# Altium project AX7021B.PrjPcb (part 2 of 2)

## Sheet PAGE03 JTAG.SchDoc
size 386 x 279 mm
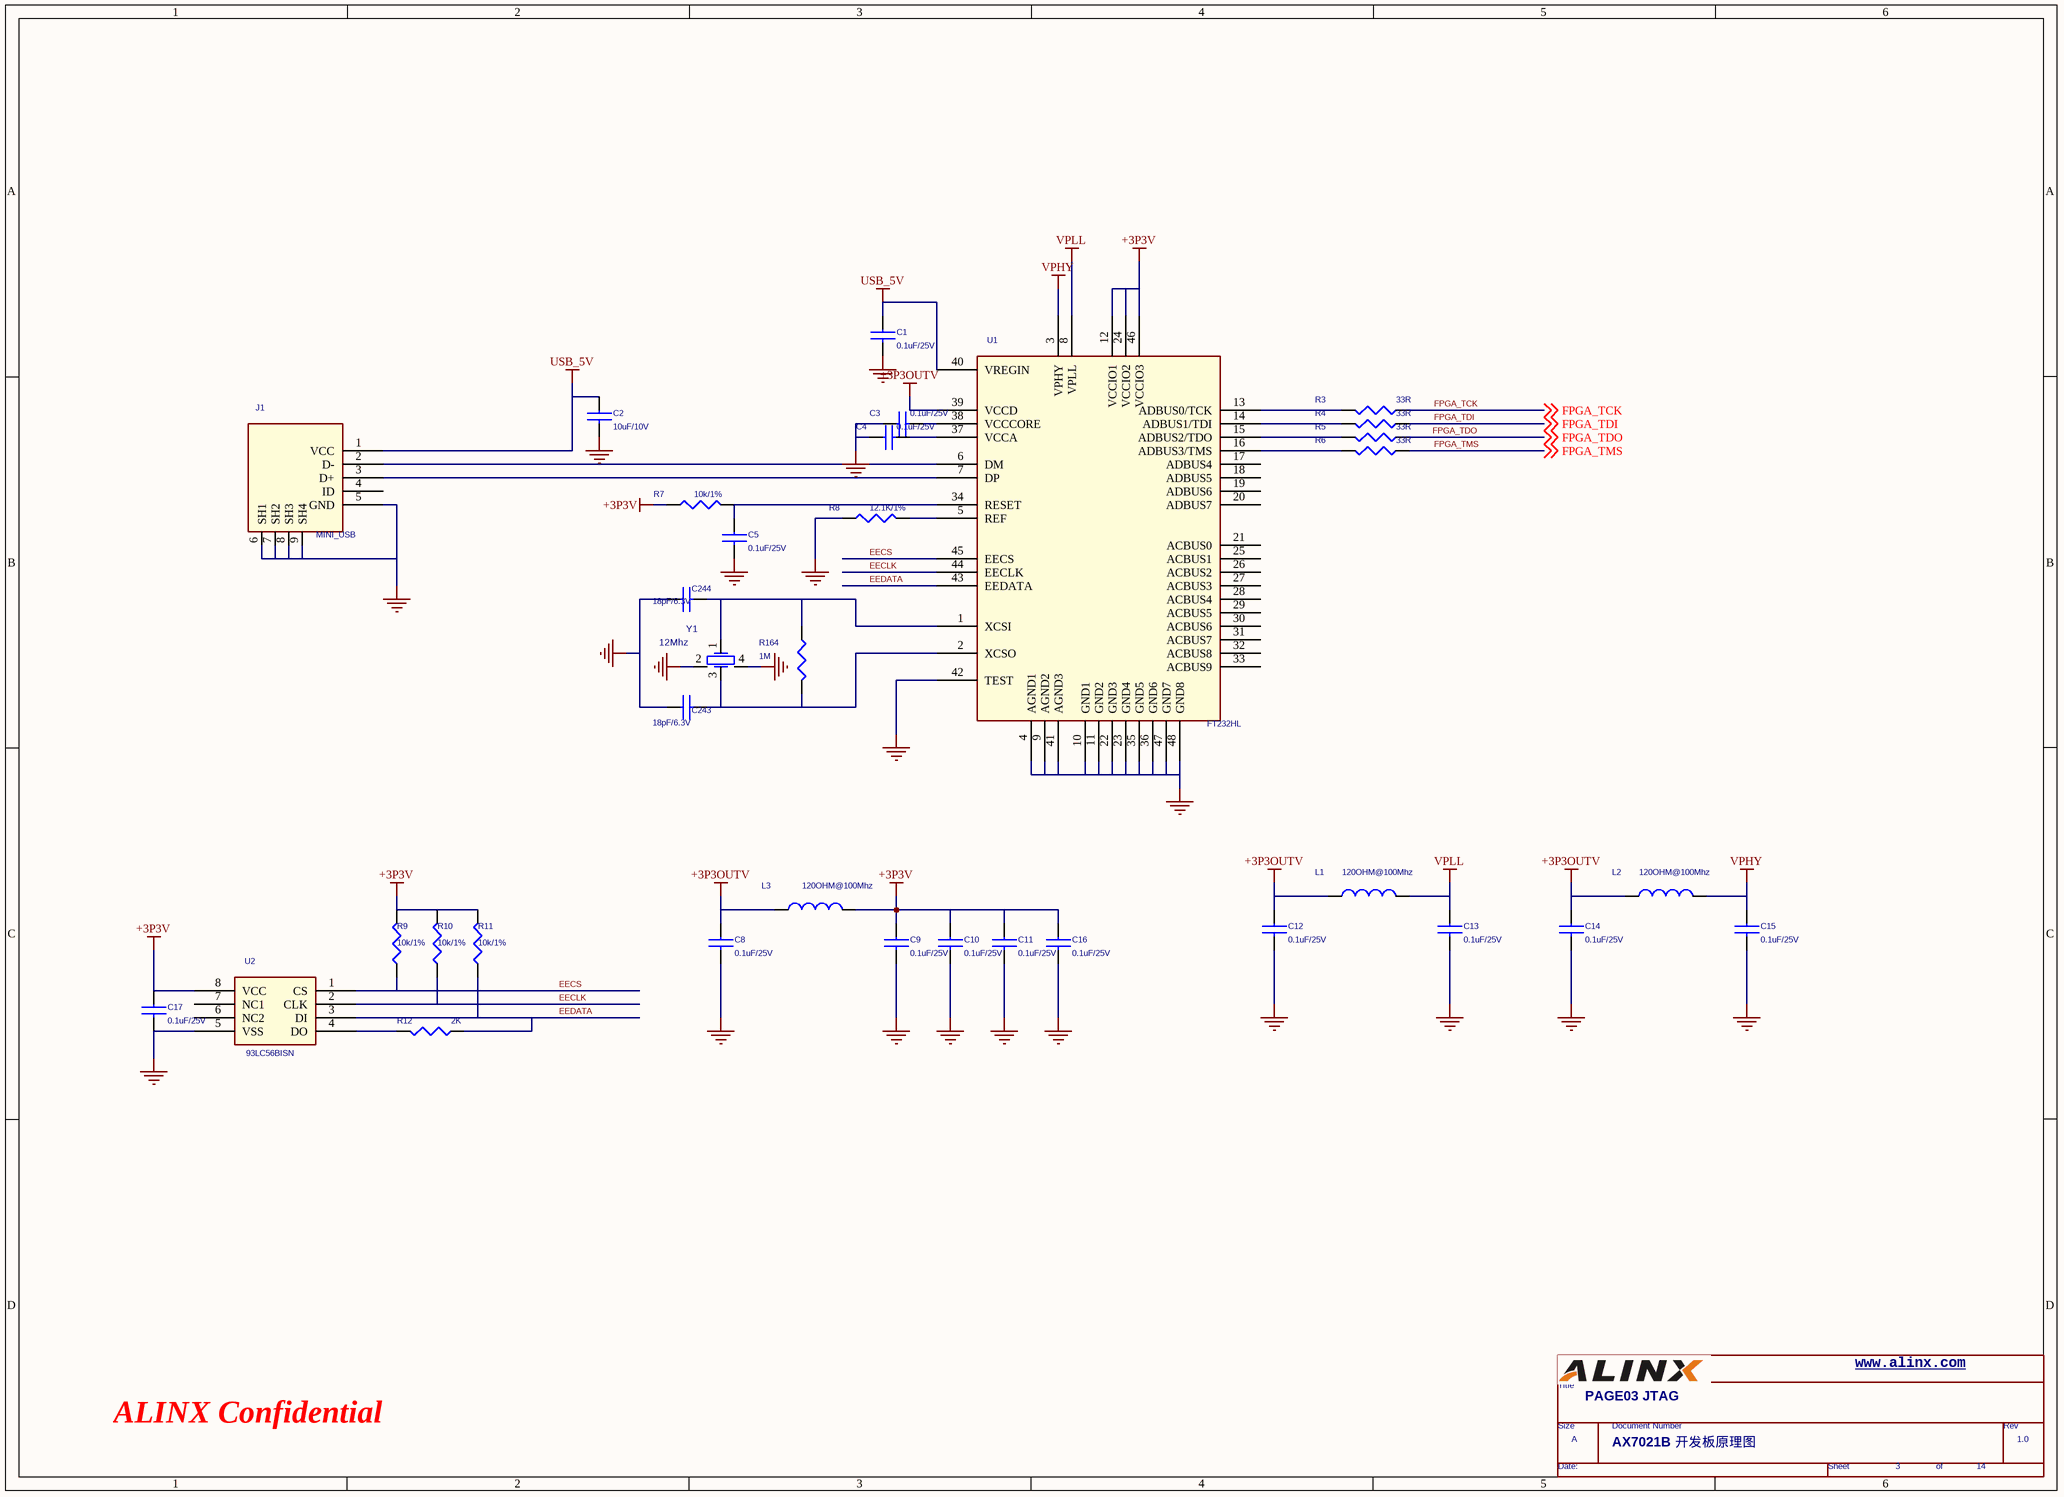
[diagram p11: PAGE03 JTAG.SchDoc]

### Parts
(Parts that share a designator on the sheet are numbered #1, #2 ... from top to bottom, then left to right.)
*#12  Doc: AX7021B 开发板原理图  RevCode: 1.0  Title: PAGE03 JTAG  Page Size: A  Page Number: 3  Page Count: 14  (hidden comment: TitleBlock0)  (graphical)
C1  0.1uF/25V  [C0402]
C2  10uF/10V  [C0603]
C3  0.1uF/25V  [C0402]
C4  0.1uF/25V  [C0402]
C5  0.1uF/25V  [C0402]
C8  0.1uF/25V  [C0402]
C9  0.1uF/25V  [C0402]
C10  0.1uF/25V  [C0402]
C11  0.1uF/25V  [C0402]
C12  0.1uF/25V  [C0402]
C13  0.1uF/25V  [C0402]
C14  0.1uF/25V  [C0402]
C15  0.1uF/25V  [C0402]
C16  0.1uF/25V  [C0402]
C17  0.1uF/25V  [C0402]
C243  18pF/6.3V  [C0402]
C244  18pF/6.3V  [C0402]
J1  MINI_USB  [mini_usb_dip]
L1  120OHM@100Mhz  [L0603]
L2  120OHM@100Mhz  [L0603]
L3  120OHM@100Mhz  [L0603]
R3  33R  [R0402]
R4  33R  [R0402]
R5  33R  [R0402]
R6  33R  [R0402]
R7  10k/1%  [R0402]
R8  12.1K/1%  [R0402]
R9  10k/1%  [R0402]
R10  10k/1%  [R0402]
R11  10k/1%  [R0402]
R12  2K  [R0402]
R164  1M  [R0402]
U1  FT232HL  [LQFP-48]
U2  93LC56BISN  [SO8]
Y1  12Mhz  [OSC3225]

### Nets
+3P3OUTV: C8.1 C12.1 C14.1 L1.1 L2.1 L3.1 U1.39(VCCD)
+3P3V: C9.1 C10.1 C11.1 C16.1 C17.1 L3.2 R7.1 R9.2 R10.2 R11.2 U1.12(VCCIO1) U1.24(VCCIO2) U1.46(VCCIO3) U2.8(VCC)
GND: C1.2 C2.2 C3.1 C4.1 C5.2 C8.2 C9.2 C10.2 C11.2 C12.2 C13.2 C14.2 C15.2 C16.2 C17.2 C243.1 C244.1 J1.5(GND) J1.6(SH1) J1.7(SH2) J1.8(SH3) J1.9(SH4) R8.1 U1.4(AGND1) U1.9(AGND2) U1.10(GND1) U1.11(GND2) U1.22(GND3) U1.23(GND4) U1.35(GND5) U1.36(GND6) U1.41(AGND3) U1.42(TEST) U1.47(GND7) U1.48(GND8) U2.5(VSS) Y1.2 Y1.4
USB_5V: C1.1 C2.1 J1.1(VCC) U1.40(VREGIN)
VPHY: C15.1 L2.2 U1.3(VPHY)
VPLL: C13.1 L1.2 U1.8(VPLL)
EECLK: R10.1 U1.44(EECLK) U2.2(CLK)
EECS: R9.1 U1.45(EECS) U2.1(CS)
EEDATA: R11.1 R12.1 U1.43(EEDATA) U2.3(DI)
FPGA_TCK: R3.1 ; off-sheet FPGA_TCK
FPGA_TDI: R4.1 ; off-sheet FPGA_TDI
FPGA_TDO: R5.1 ; off-sheet FPGA_TDO
FPGA_TMS: R6.1 ; off-sheet FPGA_TMS
NetC3_2: C3.2 U1.38(VCCCORE)
NetC4_2: C4.2 U1.37(VCCA)
NetC5_1: C5.1 R7.2 U1.34(RESET)
NetC243_2: C243.2 R164.1 U1.2(XCSO) Y1.3
NetC244_2: C244.2 R164.2 U1.1(XCSI) Y1.1
NetJ1_2: J1.2(D-) U1.6(DM)
NetJ1_3: J1.3(D+) U1.7(DP)
NetR3_2: R3.2 U1.13(ADBUS0/TCK)
NetR4_2: R4.2 U1.14(ADBUS1/TDI)
NetR5_2: R5.2 U1.15(ADBUS2/TDO)
NetR6_2: R6.2 U1.16(ADBUS3/TMS)
NetR8_2: R8.2 U1.5(REF)
NetR12_2: R12.2 U2.4(DO)

Not connected (* = marked no-connect by the designer): J1 4(ID); U1 17(ADBUS4) 18(ADBUS5) 19(ADBUS6) 20(ADBUS7) 21(ACBUS0) 25(ACBUS1) 26(ACBUS2) 27(ACBUS3) 28(ACBUS4) 29(ACBUS5) 30(ACBUS6) 31(ACBUS7) 32(ACBUS8) 33(ACBUS9); U2 6(NC2) 7(NC1)

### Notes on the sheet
- www.alinx.com
- ALINX Confidential

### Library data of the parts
C1-C5 C8-C17 C243 C244 = CAP NP: VA: 电容
J1 = USB_B_3: VA: 直插USB接口
L1-L3 = INDUCTOR_Dup1: VA: 磁珠
R3-R12 R164 = RESISTOR: VA: 电阻
U1 = FT232HL_0: VA: 芯片
U2 = 93LC56BISN_0: VA: 芯片
Y1 = X3_0_Dup1: VA: 无源晶振

## Sheet PAGE02 Board Connector.SchDoc
size 386 x 279 mm
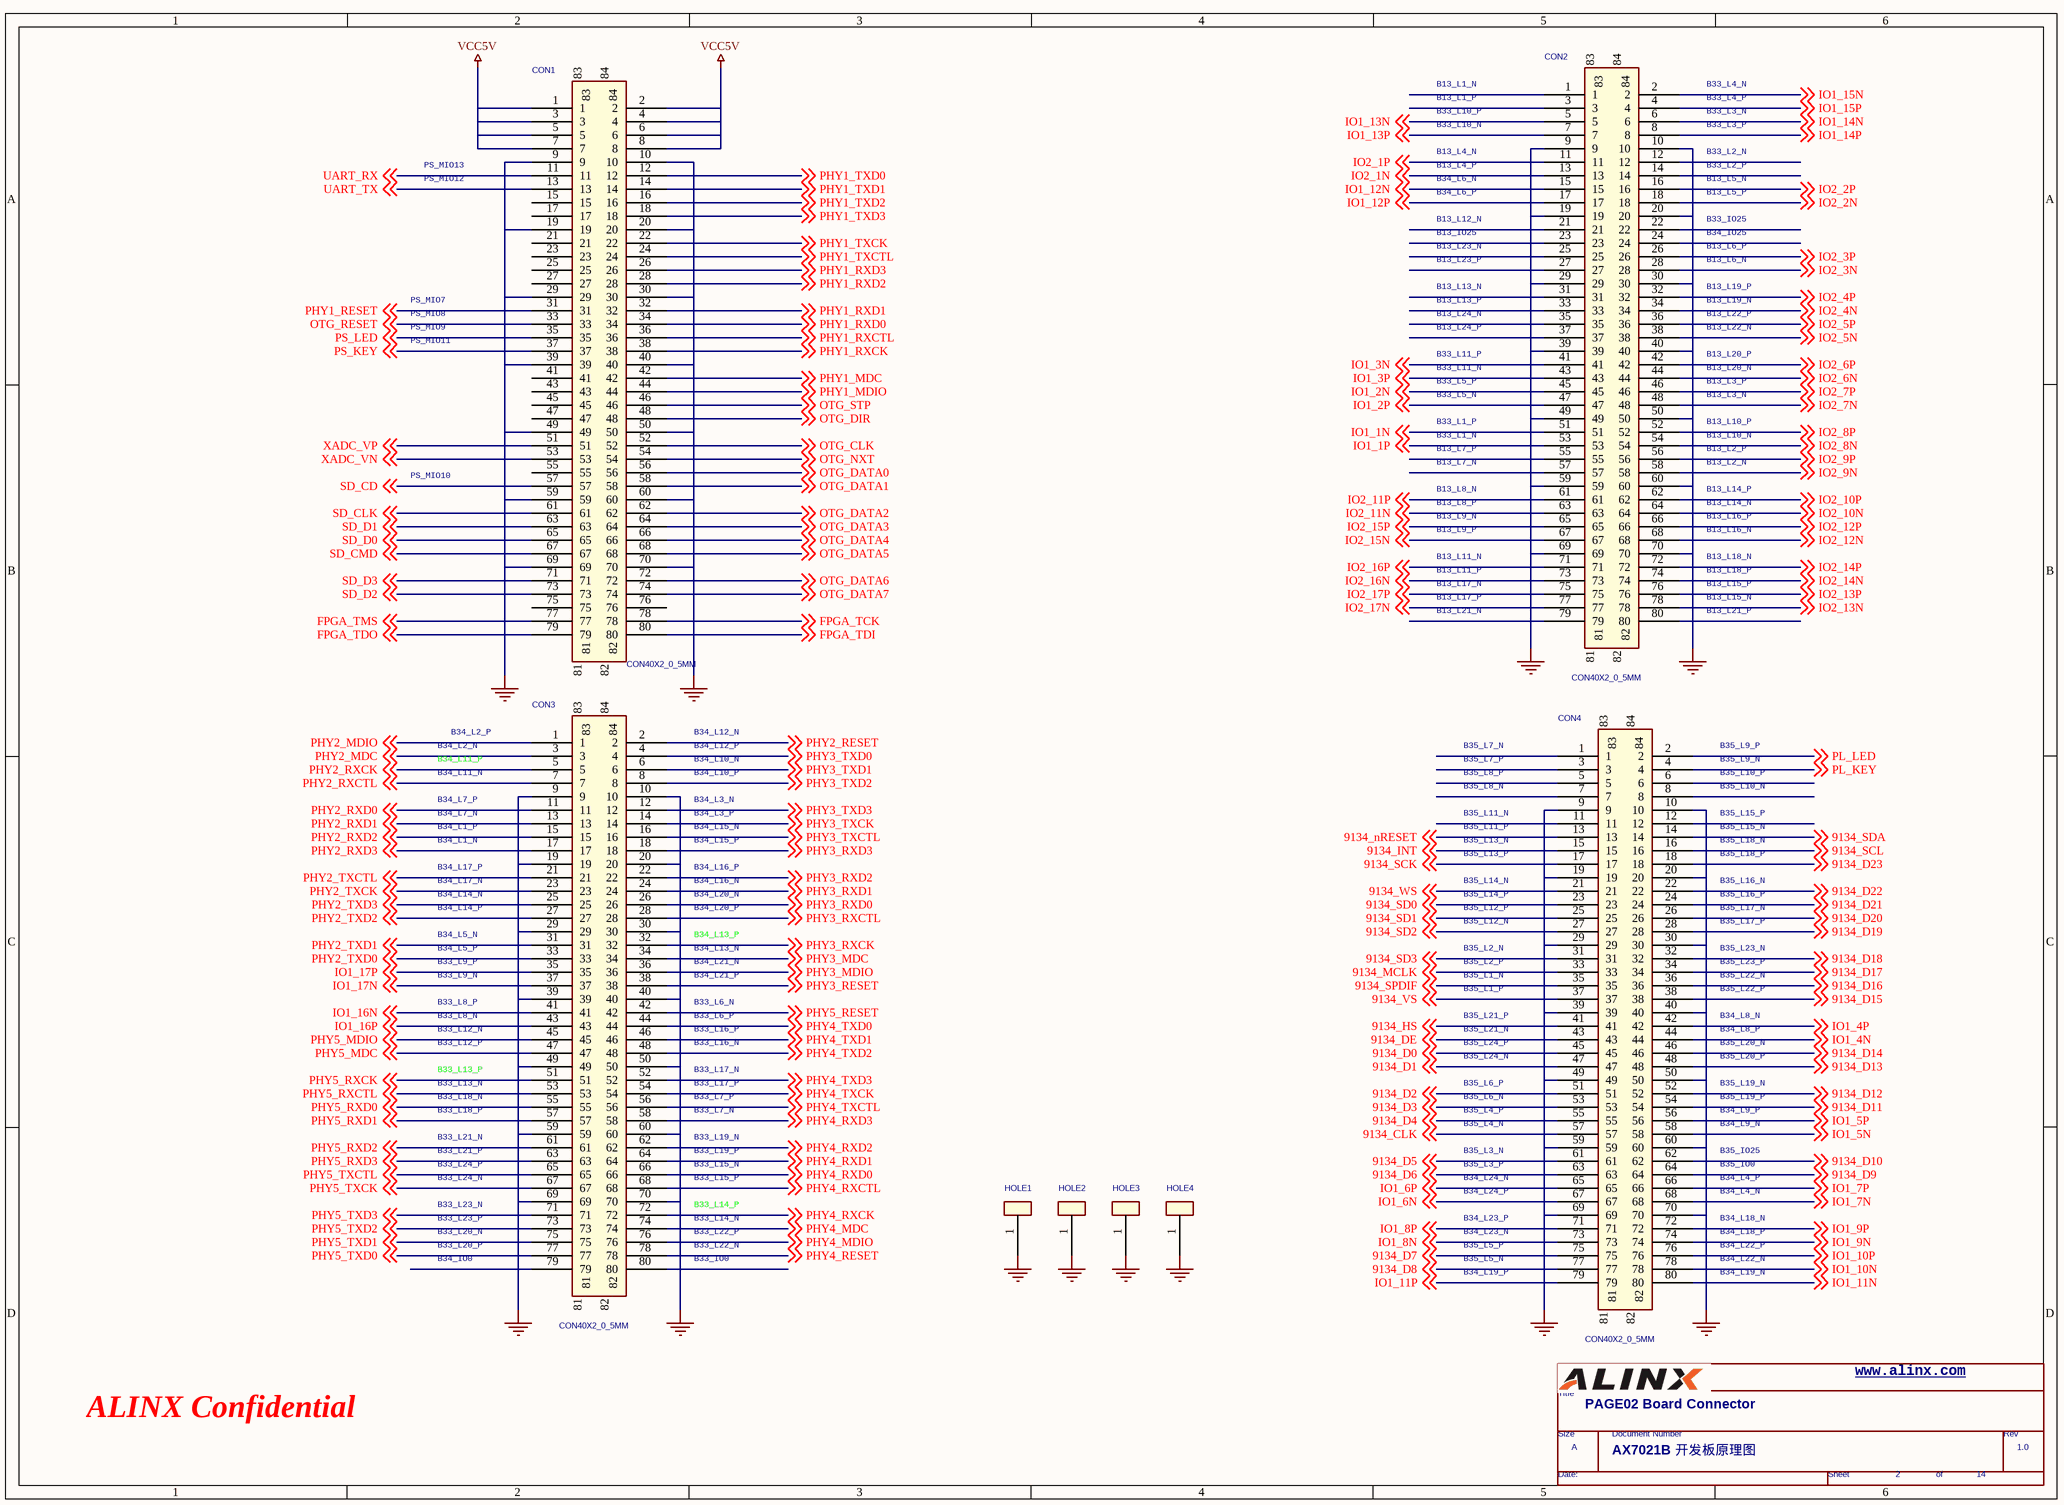
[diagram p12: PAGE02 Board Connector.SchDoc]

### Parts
(Parts that share a designator on the sheet are numbered #1, #2 ... from top to bottom, then left to right.)
*#13  Doc: AX7021B 开发板原理图  RevCode: 1.0  Title: PAGE02 Board Connector  Page Size: A  Page Number: 2  Page Count: 14  (hidden comment: TitleBlock0)  (graphical)
CON1  CON40X2_0_5MM  [CON40X2_0_8MM]
CON2  CON40X2_0_5MM  [CON40X2_0_8MM]
CON3  CON40X2_0_5MM  [CON40X2_0_8MM]
CON4  CON40X2_0_5MM  [CON40X2_0_8MM]
HOLE1  NC  [FPAD_1]  (value not drawn)
HOLE2  NC  [FPAD_1]  (value not drawn)
HOLE3  NC  [FPAD_1]  (value not drawn)
HOLE4  NC  [FPAD_1]  (value not drawn)

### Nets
GND: CON1.9 CON1.10 CON1.19 CON1.20 CON1.29 CON1.30 CON1.39 CON1.40 CON1.49 CON1.50 CON1.59 CON1.60 CON1.69 CON1.70 CON2.9 CON2.10 CON2.19 CON2.20 CON2.29 CON2.30 CON2.39 CON2.40 CON2.49 CON2.50 CON2.59 CON2.60 CON2.69 CON2.70 CON3.9 CON3.10 CON3.19 CON3.20 CON3.29 CON3.30 CON3.39 CON3.40 CON3.49 CON3.50 CON3.59 CON3.60 CON3.69 CON3.70 CON4.9 CON4.10 CON4.19 CON4.20 CON4.29 CON4.30 CON4.39 CON4.40 CON4.49 CON4.50 CON4.59 CON4.60 CON4.69 CON4.70 HOLE1.1 HOLE2.1 HOLE3.1 HOLE4.1
VCC5V: CON1.1 CON1.2 CON1.3 CON1.4 CON1.5 CON1.6 CON1.7 CON1.8
9134_CLK: CON4.57 ; off-sheet 9134_CLK
9134_D0: CON4.45 ; off-sheet 9134_D0
9134_D1: CON4.47 ; off-sheet 9134_D1
9134_D2: CON4.51 ; off-sheet 9134_D2
9134_D3: CON4.53 ; off-sheet 9134_D3
9134_D4: CON4.55 ; off-sheet 9134_D4
9134_D5: CON4.61 ; off-sheet 9134_D5
9134_D6: CON4.63 ; off-sheet 9134_D6
9134_D7: CON4.75 ; off-sheet 9134_D7
9134_D8: CON4.77 ; off-sheet 9134_D8
9134_D9: CON4.64 ; off-sheet 9134_D9
9134_D10: CON4.62 ; off-sheet 9134_D10
9134_D11: CON4.54 ; off-sheet 9134_D11
9134_D12: CON4.52 ; off-sheet 9134_D12
9134_D13: CON4.48 ; off-sheet 9134_D13
9134_D14: CON4.46 ; off-sheet 9134_D14
9134_D15: CON4.38 ; off-sheet 9134_D15
9134_D16: CON4.36 ; off-sheet 9134_D16
9134_D17: CON4.34 ; off-sheet 9134_D17
9134_D18: CON4.32 ; off-sheet 9134_D18
9134_D19: CON4.28 ; off-sheet 9134_D19
9134_D20: CON4.26 ; off-sheet 9134_D20
9134_D21: CON4.24 ; off-sheet 9134_D21
9134_D22: CON4.22 ; off-sheet 9134_D22
9134_D23: CON4.18 ; off-sheet 9134_D23
9134_DE: CON4.43 ; off-sheet 9134_DE
9134_HS: CON4.41 ; off-sheet 9134_HS
9134_INT: CON4.15 ; off-sheet 9134_INT
9134_MCLK: CON4.33 ; off-sheet 9134_MCLK
9134_nRESET: CON4.13 ; off-sheet 9134_nRESET
9134_SCK: CON4.17 ; off-sheet 9134_SCK
9134_SCL: CON4.16 ; off-sheet 9134_SCL
9134_SD0: CON4.23 ; off-sheet 9134_SD0
9134_SD1: CON4.25 ; off-sheet 9134_SD1
9134_SD2: CON4.27 ; off-sheet 9134_SD2
9134_SD3: CON4.31 ; off-sheet 9134_SD3
9134_SDA: CON4.14 ; off-sheet 9134_SDA
9134_SPDIF: CON4.35 ; off-sheet 9134_SPDIF
9134_VS: CON4.37 ; off-sheet 9134_VS
9134_WS: CON4.21 ; off-sheet 9134_WS
FPGA_TCK: CON1.78 ; off-sheet FPGA_TCK
FPGA_TDI: CON1.80 ; off-sheet FPGA_TDI
FPGA_TDO: CON1.79 ; off-sheet FPGA_TDO
FPGA_TMS: CON1.77 ; off-sheet FPGA_TMS
IO1_1N: CON2.51 ; off-sheet IO1_1N
IO1_1P: CON2.53 ; off-sheet IO1_1P
IO1_2N: CON2.45 ; off-sheet IO1_2N
IO1_2P: CON2.47 ; off-sheet IO1_2P
IO1_3N: CON2.41 ; off-sheet IO1_3N
IO1_3P: CON2.43 ; off-sheet IO1_3P
IO1_4N: CON4.44 ; off-sheet IO1_4N
IO1_4P: CON4.42 ; off-sheet IO1_4P
IO1_5N: CON4.58 ; off-sheet IO1_5N
IO1_5P: CON4.56 ; off-sheet IO1_5P
IO1_6N: CON4.67 ; off-sheet IO1_6N
IO1_6P: CON4.65 ; off-sheet IO1_6P
IO1_7N: CON4.68 ; off-sheet IO1_7N
IO1_7P: CON4.66 ; off-sheet IO1_7P
IO1_8N: CON4.73 ; off-sheet IO1_8N
IO1_8P: CON4.71 ; off-sheet IO1_8P
IO1_9N: CON4.74 ; off-sheet IO1_9N
IO1_9P: CON4.72 ; off-sheet IO1_9P
IO1_10N: CON4.78 ; off-sheet IO1_10N
IO1_10P: CON4.76 ; off-sheet IO1_10P
IO1_11N: CON4.80 ; off-sheet IO1_11N
IO1_11P: CON4.79 ; off-sheet IO1_11P
IO1_12N: CON2.15 ; off-sheet IO1_12N
IO1_12P: CON2.17 ; off-sheet IO1_12P
IO1_13N: CON2.5 ; off-sheet IO1_13N
IO1_13P: CON2.7 ; off-sheet IO1_13P
IO1_14N: CON2.6 ; off-sheet IO1_14N
IO1_14P: CON2.8 ; off-sheet IO1_14P
IO1_15N: CON2.2 ; off-sheet IO1_15N
IO1_15P: CON2.4 ; off-sheet IO1_15P
IO1_16N: CON3.41 ; off-sheet IO1_16N
IO1_16P: CON3.43 ; off-sheet IO1_16P
IO1_17N: CON3.37 ; off-sheet IO1_17N
IO1_17P: CON3.35 ; off-sheet IO1_17P
IO2_1N: CON2.13 ; off-sheet IO2_1N
IO2_1P: CON2.11 ; off-sheet IO2_1P
IO2_2N: CON2.18 ; off-sheet IO2_2N
IO2_2P: CON2.16 ; off-sheet IO2_2P
IO2_3N: CON2.28 ; off-sheet IO2_3N
IO2_3P: CON2.26 ; off-sheet IO2_3P
IO2_4N: CON2.34 ; off-sheet IO2_4N
IO2_4P: CON2.32 ; off-sheet IO2_4P
IO2_5N: CON2.38 ; off-sheet IO2_5N
IO2_5P: CON2.36 ; off-sheet IO2_5P
IO2_6N: CON2.44 ; off-sheet IO2_6N
IO2_6P: CON2.42 ; off-sheet IO2_6P
IO2_7N: CON2.48 ; off-sheet IO2_7N
IO2_7P: CON2.46 ; off-sheet IO2_7P
IO2_8N: CON2.54 ; off-sheet IO2_8N
IO2_8P: CON2.52 ; off-sheet IO2_8P
IO2_9N: CON2.58 ; off-sheet IO2_9N
IO2_9P: CON2.56 ; off-sheet IO2_9P
IO2_10N: CON2.64 ; off-sheet IO2_10N
IO2_10P: CON2.62 ; off-sheet IO2_10P
IO2_11N: CON2.63 ; off-sheet IO2_11N
IO2_11P: CON2.61 ; off-sheet IO2_11P
IO2_12N: CON2.68 ; off-sheet IO2_12N
IO2_12P: CON2.66 ; off-sheet IO2_12P
IO2_13N: CON2.78 ; off-sheet IO2_13N
IO2_13P: CON2.76 ; off-sheet IO2_13P
IO2_14N: CON2.74 ; off-sheet IO2_14N
IO2_14P: CON2.72 ; off-sheet IO2_14P
IO2_15N: CON2.67 ; off-sheet IO2_15N
IO2_15P: CON2.65 ; off-sheet IO2_15P
IO2_16N: CON2.73 ; off-sheet IO2_16N
IO2_16P: CON2.71 ; off-sheet IO2_16P
IO2_17N: CON2.77 ; off-sheet IO2_17N
IO2_17P: CON2.75 ; off-sheet IO2_17P
OTG_CLK: CON1.52 ; off-sheet OTG_CLK
OTG_DATA0: CON1.56 ; off-sheet OTG_DATA0
OTG_DATA1: CON1.58 ; off-sheet OTG_DATA1
OTG_DATA2: CON1.62 ; off-sheet OTG_DATA2
OTG_DATA3: CON1.64 ; off-sheet OTG_DATA3
OTG_DATA4: CON1.66 ; off-sheet OTG_DATA4
OTG_DATA5: CON1.68 ; off-sheet OTG_DATA5
OTG_DATA6: CON1.72 ; off-sheet OTG_DATA6
OTG_DATA7: CON1.74 ; off-sheet OTG_DATA7
OTG_DIR: CON1.48 ; off-sheet OTG_DIR
OTG_NXT: CON1.54 ; off-sheet OTG_NXT
OTG_RESET: CON1.33 ; off-sheet OTG_RESET
OTG_STP: CON1.46 ; off-sheet OTG_STP
PHY1_MDC: CON1.42 ; off-sheet PHY1_MDC
PHY1_MDIO: CON1.44 ; off-sheet PHY1_MDIO
PHY1_RESET: CON1.31 ; off-sheet PHY1_RESET
PHY1_RXCK: CON1.38 ; off-sheet PHY1_RXCK
PHY1_RXCTL: CON1.36 ; off-sheet PHY1_RXCTL
PHY1_RXD0: CON1.34 ; off-sheet PHY1_RXD0
PHY1_RXD1: CON1.32 ; off-sheet PHY1_RXD1
PHY1_RXD2: CON1.28 ; off-sheet PHY1_RXD2
PHY1_RXD3: CON1.26 ; off-sheet PHY1_RXD3
PHY1_TXCK: CON1.22 ; off-sheet PHY1_TXCK
PHY1_TXCTL: CON1.24 ; off-sheet PHY1_TXCTL
PHY1_TXD0: CON1.12 ; off-sheet PHY1_TXD0
PHY1_TXD1: CON1.14 ; off-sheet PHY1_TXD1
PHY1_TXD2: CON1.16 ; off-sheet PHY1_TXD2
PHY1_TXD3: CON1.18 ; off-sheet PHY1_TXD3
PHY2_MDC: CON3.3 ; off-sheet PHY2_MDC
PHY2_MDIO: CON3.1 ; off-sheet PHY2_MDIO
PHY2_RESET: CON3.2 ; off-sheet PHY2_RESET
PHY2_RXCK: CON3.5 ; off-sheet PHY2_RXCK
PHY2_RXCTL: CON3.7 ; off-sheet PHY2_RXCTL
PHY2_RXD0: CON3.11 ; off-sheet PHY2_RXD0
PHY2_RXD1: CON3.13 ; off-sheet PHY2_RXD1
PHY2_RXD2: CON3.15 ; off-sheet PHY2_RXD2
PHY2_RXD3: CON3.17 ; off-sheet PHY2_RXD3
PHY2_TXCK: CON3.23 ; off-sheet PHY2_TXCK
PHY2_TXCTL: CON3.21 ; off-sheet PHY2_TXCTL
PHY2_TXD0: CON3.33 ; off-sheet PHY2_TXD0
PHY2_TXD1: CON3.31 ; off-sheet PHY2_TXD1
PHY2_TXD2: CON3.27 ; off-sheet PHY2_TXD2
PHY2_TXD3: CON3.25 ; off-sheet PHY2_TXD3
PHY3_MDC: CON3.34 ; off-sheet PHY3_MDC
PHY3_MDIO: CON3.36 ; off-sheet PHY3_MDIO
PHY3_RESET: CON3.38 ; off-sheet PHY3_RESET
PHY3_RXCK: CON3.32 ; off-sheet PHY3_RXCK
PHY3_RXCTL: CON3.28 ; off-sheet PHY3_RXCTL
PHY3_RXD0: CON3.26 ; off-sheet PHY3_RXD0
PHY3_RXD1: CON3.24 ; off-sheet PHY3_RXD1
PHY3_RXD2: CON3.22 ; off-sheet PHY3_RXD2
PHY3_RXD3: CON3.18 ; off-sheet PHY3_RXD3
PHY3_TXCK: CON3.14 ; off-sheet PHY3_TXCK
PHY3_TXCTL: CON3.16 ; off-sheet PHY3_TXCTL
PHY3_TXD0: CON3.4 ; off-sheet PHY3_TXD0
PHY3_TXD1: CON3.6 ; off-sheet PHY3_TXD1
PHY3_TXD2: CON3.8 ; off-sheet PHY3_TXD2
PHY3_TXD3: CON3.12 ; off-sheet PHY3_TXD3
PHY4_MDC: CON3.74 ; off-sheet PHY4_MDC
PHY4_MDIO: CON3.76 ; off-sheet PHY4_MDIO
PHY4_RESET: CON3.78 ; off-sheet PHY4_RESET
PHY4_RXCK: CON3.72 ; off-sheet PHY4_RXCK
PHY4_RXCTL: CON3.68 ; off-sheet PHY4_RXCTL
PHY4_RXD0: CON3.66 ; off-sheet PHY4_RXD0
PHY4_RXD1: CON3.64 ; off-sheet PHY4_RXD1
PHY4_RXD2: CON3.62 ; off-sheet PHY4_RXD2
PHY4_RXD3: CON3.58 ; off-sheet PHY4_RXD3
PHY4_TXCK: CON3.54 ; off-sheet PHY4_TXCK
PHY4_TXCTL: CON3.56 ; off-sheet PHY4_TXCTL
PHY4_TXD0: CON3.44 ; off-sheet PHY4_TXD0
PHY4_TXD1: CON3.46 ; off-sheet PHY4_TXD1
PHY4_TXD2: CON3.48 ; off-sheet PHY4_TXD2
PHY4_TXD3: CON3.52 ; off-sheet PHY4_TXD3
PHY5_MDC: CON3.47 ; off-sheet PHY5_MDC
PHY5_MDIO: CON3.45 ; off-sheet PHY5_MDIO
PHY5_RESET: CON3.42 ; off-sheet PHY5_RESET
PHY5_RXCK: CON3.51 ; off-sheet PHY5_RXCK
PHY5_RXCTL: CON3.53 ; off-sheet PHY5_RXCTL
PHY5_RXD0: CON3.55 ; off-sheet PHY5_RXD0
PHY5_RXD1: CON3.57 ; off-sheet PHY5_RXD1
PHY5_RXD2: CON3.61 ; off-sheet PHY5_RXD2
PHY5_RXD3: CON3.63 ; off-sheet PHY5_RXD3
PHY5_TXCK: CON3.67 ; off-sheet PHY5_TXCK
PHY5_TXCTL: CON3.65 ; off-sheet PHY5_TXCTL
PHY5_TXD0: CON3.77 ; off-sheet PHY5_TXD0
PHY5_TXD1: CON3.75 ; off-sheet PHY5_TXD1
PHY5_TXD2: CON3.73 ; off-sheet PHY5_TXD2
PHY5_TXD3: CON3.71 ; off-sheet PHY5_TXD3
PL_KEY: CON4.4 ; off-sheet PL_KEY
PL_LED: CON4.2 ; off-sheet PL_LED
PS_KEY: CON1.37 ; off-sheet PS_KEY
PS_LED: CON1.35 ; off-sheet PS_LED
SD_CD: CON1.57 ; off-sheet SD_CD
SD_CLK: CON1.61 ; off-sheet SD_CLK
SD_CMD: CON1.67 ; off-sheet SD_CMD
SD_D0: CON1.65 ; off-sheet SD_D0
SD_D1: CON1.63 ; off-sheet SD_D1
SD_D2: CON1.73 ; off-sheet SD_D2
SD_D3: CON1.71 ; off-sheet SD_D3
UART_RX: CON1.11 ; off-sheet UART_RX
UART_TX: CON1.13 ; off-sheet UART_TX
XADC_VN: CON1.53 ; off-sheet XADC_VN
XADC_VP: CON1.51 ; off-sheet XADC_VP

Not connected (* = marked no-connect by the designer): CON1 15 17 21 23 25 27 41 43 45 47 55 75 76 81 82 83 84; CON2 1 3 12 14 21 22 23 24 25 27 31 33 35 37 55 57 79 80 81 82 83 84; CON3 79 80 81 82 83 84; CON4 1 3 5 6 7 8 11 12 81 82 83 84

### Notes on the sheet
- B13_L1_N
- B13_L1_P
- B33_L4_N
- B33_L4_P
- PS_MIO13
- B33_L10_P
- B33_L10_N
- B13_L4_N
- B13_L4_P
- B33_L3_P
- B33_L3_N
- B33_L2_N
- B33_L2_P
- PS_MIO12
- B13_L12_N
- B34_L6_N
- B13_IO25
- B34_L6_P
- B33_IO25
- B13_L5_P
- B13_L5_N
- B34_IO25
- PS_MIO7
- B13_L13_N
- B13_L13_P
- B13_L23_P
- B13_L23_N
- B13_L6_N
- B13_L6_P
- B13_L19_P
- B13_L19_N
- PS_MIO11
- PS_MIO8
- PS_MIO9
- B33_L11_N
- B33_L11_P
- B13_L24_N
- B13_L24_P
- B13_L20_P
- B13_L20_N
- B13_L22_P
- B13_L22_N
- B33_L5_N
- B33_L5_P
- B33_L1_P
- B33_L1_N
- B13_L10_P
- B13_L10_N
- B13_L3_P
- B13_L3_N
- PS_MIO10
- B13_L7_N
- B13_L7_P
- B13_L8_N
- B13_L8_P
- B13_L14_P
- B13_L14_N
- B13_L2_P
- B13_L2_N
- B13_L9_N
- B13_L9_P
- B13_L11_N
- B13_L11_P
- B13_L16_P
- B13_L16_N
- B13_L18_N
- B13_L18_P
- B13_L17_N
- B13_L17_P
- B13_L21_N
- B13_L15_P
- B13_L15_N
- B13_L21_P
- B34_L2_N
- B34_L11_N
- B34_L11_P
- B34_L2_P
- B34_L12_N
- B34_L12_P
- B34_L10_P
- B34_L10_N
- B35_L7_N
- B35_L7_P
- B35_L8_P
- B35_L10_P
- B35_L9_P
- B35_L9_N
- B34_L7_P
- B34_L7_N
- B34_L1_N
- B34_L1_P
- B34_L3_N
- B34_L3_P
- B34_L15_N
- B34_L15_P
- B35_L8_N
- B35_L11_N
- B35_L11_P
- B35_L13_N
- B35_L18_N
- B35_L15_P
- B35_L15_N
- B35_L10_N
- B34_L17_N
- B34_L17_P
- B34_L14_N
- B34_L14_P
- B34_L20_N
- B34_L20_P
- B34_L16_N
- B34_L16_P
- B35_L13_P
- B35_L14_N
- B35_L14_P
- B35_L12_P
- B35_L17_N
- B35_L16_N
- B35_L16_P
- B35_L18_P
- B33_L9_N
- B34_L5_N
- B34_L5_P
- B33_L9_P
- B34_L21_P
- B34_L21_N
- B34_L13_N
- B34_L13_P
- B35_L12_N
- B35_L1_N
- B35_L2_N
- B35_L2_P
- B35_L23_N
- B35_L23_P
- B35_L22_N
- B35_L17_P
- B33_L8_P
- B33_L8_N
- B33_L12_N
- B33_L12_P
- B33_L16_N
- B33_L16_P
- B33_L6_N
- B33_L6_P
- B35_L24_P
- B35_L21_P
- B35_L21_N
- B35_L1_P
- B35_L20_N
- B34_L8_P
- B34_L8_N
- B35_L22_P
- B33_L18_N
- B33_L18_P
- B33_L13_P
- B33_L13_N
- B33_L17_N
- B33_L17_P
- B33_L7_N
- B33_L7_P
- B35_L24_N
- B35_L6_P
- B35_L6_N
- B35_L4_P
- B34_L9_P
- B35_L19_P
- B35_L19_N
- B35_L20_P
- B33_L21_P
- B33_L24_P
- B33_L24_N
- B33_L21_N
- B33_L15_P
- B33_L15_N
- B33_L19_N
- B33_L19_P
- B34_L24_N
- B35_L4_N
- B35_L3_N
- B35_L3_P
- B35_IO25
- B35_IO0
- B34_L4_P
- B34_L9_N
- B33_L23_N
- B33_L23_P
- B33_L20_N
- B33_L20_P
- B33_L22_P
- B33_L22_N
- B33_L14_N
- B33_L14_P
- B34_L23_P
- B34_L23_N
- B34_L24_P
- B35_L5_P
- B34_L22_P
- B34_L18_P
- B34_L18_N
- B34_L4_N
- B34_IO0
- B33_IO0
- B35_L5_N
- B34_L19_P
- B34_L22_N
- B34_L19_N
- www.alinx.com
- ALINX Confidential

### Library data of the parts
CON1-CON4 = CON40X2_0_1: VA: 2x40PIN连接器底板
HOLE1-HOLE4 = TEST POINT

## Sheet PAGE01 Block Diagram.SchDoc
size 406 x 304 mm
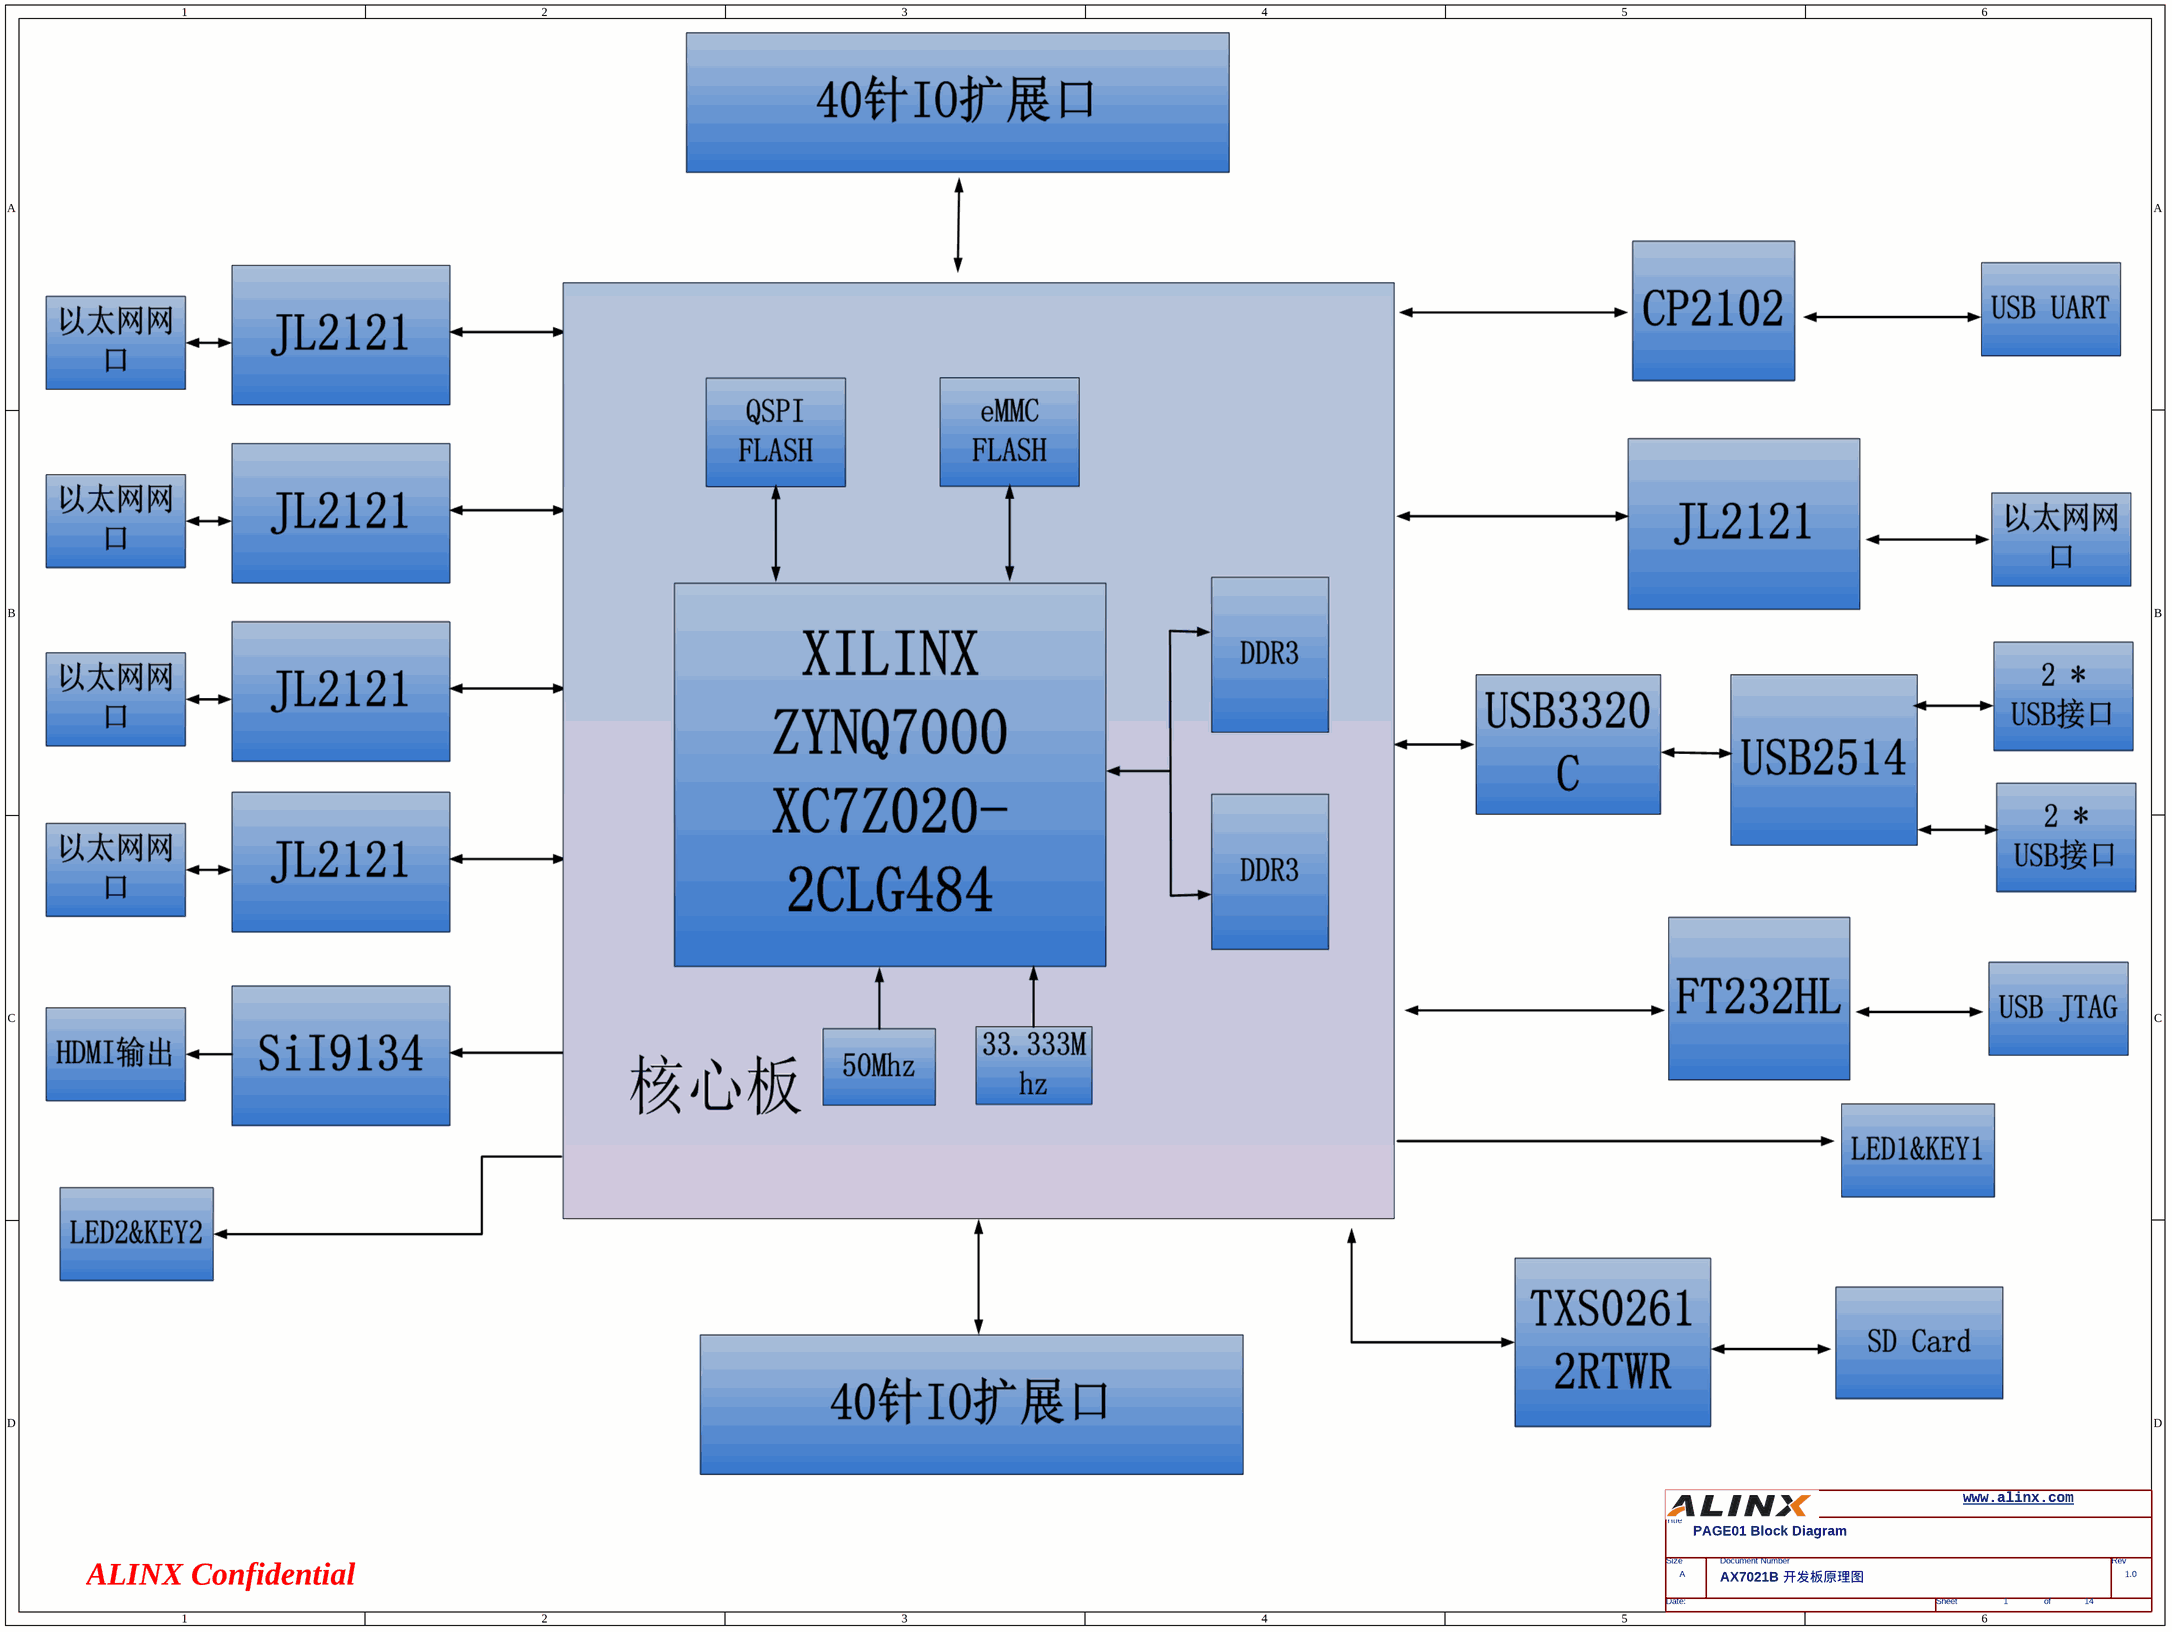
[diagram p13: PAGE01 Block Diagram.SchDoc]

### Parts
(Parts that share a designator on the sheet are numbered #1, #2 ... from top to bottom, then left to right.)
*#14  Doc: AX7021B 开发板原理图  RevCode: 1.0  Title: PAGE01 Block Diagram  Page Size: A  Page Number: 1  Page Count: 14  (hidden comment: TitleBlock0)  (graphical)

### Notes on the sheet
- www.alinx.com
- ALINX Confidential

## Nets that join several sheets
GND: PAGE14 Power (33 pins), PAGE13 EX Connector (10 pins), PAGE12 KEY and LED (KEY1.1 KEY1.2 KEY2.1 KEY2.2), PAGE11 PL Ethernet5 (32 pins), PAGE10 PL Ethernet4 (32 pins), PAGE09 PL Ethernet3 (32 pins), PAGE08 PL Ethernet2 (32 pins), PAGE07 HDMI OUT (51 pins), PAGE06 HOST USB X 4 (58 pins), PAGE05 PS Ethernet1 (30 pins), PAGE04 SD Card and UART (24 pins), PAGE03 JTAG (38 pins), PAGE02 Board Connector (60 pins)
RGMII_VCC: PAGE14 Power (C187.1 C188.1 U19.5), PAGE11 PL Ethernet5 (L81.1), PAGE10 PL Ethernet4 (L77.1), PAGE09 PL Ethernet3 (L73.1), PAGE08 PL Ethernet2 (L69.1)
VCC1V8: PAGE14 Power (7 pins), PAGE07 HDMI OUT (C81.1 L8.2 L9.2), PAGE06 HOST USB X 4 (10 pins), PAGE05 PS Ethernet1 (L65.1), PAGE04 SD Card and UART (C24.1 U5.5)
VCC3V3: PAGE14 Power (7 pins), PAGE13 EX Connector (6 pins), PAGE12 KEY and LED (LED1.1 LED2.1 R119.2 R123.2), PAGE11 PL Ethernet5 (6 pins), PAGE10 PL Ethernet4 (6 pins), PAGE09 PL Ethernet3 (6 pins), PAGE08 PL Ethernet2 (6 pins), PAGE07 HDMI OUT (L7.1 R48.2 R49.2), PAGE06 HOST USB X 4 (19 pins), PAGE05 PS Ethernet1 (8 pins), PAGE04 SD Card and UART (14 pins)
VCC5V: PAGE14 Power (11 pins), PAGE13 EX Connector (C190.1 C192.1 J15.2 J16.2), PAGE07 HDMI OUT (F1.1 U9.45), PAGE06 HOST USB X 4 (C61.1 U8.5), PAGE02 Board Connector (8 pins)
9134_CLK: PAGE07 HDMI OUT (U9.88), PAGE02 Board Connector (CON4.57)
9134_D0: PAGE07 HDMI OUT (U9.94), PAGE02 Board Connector (CON4.45)
9134_D1: PAGE07 HDMI OUT (U9.93), PAGE02 Board Connector (CON4.47)
9134_D2: PAGE07 HDMI OUT (U9.92), PAGE02 Board Connector (CON4.51)
9134_D3: PAGE07 HDMI OUT (U9.91), PAGE02 Board Connector (CON4.53)
9134_D4: PAGE07 HDMI OUT (U9.90), PAGE02 Board Connector (CON4.55)
9134_D5: PAGE07 HDMI OUT (U9.86), PAGE02 Board Connector (CON4.61)
9134_D6: PAGE07 HDMI OUT (U9.85), PAGE02 Board Connector (CON4.63)
9134_D7: PAGE07 HDMI OUT (U9.84), PAGE02 Board Connector (CON4.75)
9134_D8: PAGE07 HDMI OUT (U9.79), PAGE02 Board Connector (CON4.77)
9134_D9: PAGE07 HDMI OUT (U9.78), PAGE02 Board Connector (CON4.64)
9134_D10: PAGE07 HDMI OUT (U9.77), PAGE02 Board Connector (CON4.62)
9134_D11: PAGE07 HDMI OUT (U9.75), PAGE02 Board Connector (CON4.54)
9134_D12: PAGE07 HDMI OUT (U9.74), PAGE02 Board Connector (CON4.52)
9134_D13: PAGE07 HDMI OUT (U9.73), PAGE02 Board Connector (CON4.48)
9134_D14: PAGE07 HDMI OUT (U9.72), PAGE02 Board Connector (CON4.46)
9134_D15: PAGE07 HDMI OUT (U9.71), PAGE02 Board Connector (CON4.38)
9134_D16: PAGE07 HDMI OUT (U9.63), PAGE02 Board Connector (CON4.36)
9134_D17: PAGE07 HDMI OUT (U9.62), PAGE02 Board Connector (CON4.34)
9134_D18: PAGE07 HDMI OUT (U9.61), PAGE02 Board Connector (CON4.32)
9134_D19: PAGE07 HDMI OUT (U9.60), PAGE02 Board Connector (CON4.28)
9134_D20: PAGE07 HDMI OUT (U9.59), PAGE02 Board Connector (CON4.26)
9134_D21: PAGE07 HDMI OUT (U9.58), PAGE02 Board Connector (CON4.24)
9134_D22: PAGE07 HDMI OUT (U9.57), PAGE02 Board Connector (CON4.22)
9134_D23: PAGE07 HDMI OUT (U9.56), PAGE02 Board Connector (CON4.18)
9134_DE: PAGE07 HDMI OUT (U9.1), PAGE02 Board Connector (CON4.43)
9134_HS: PAGE07 HDMI OUT (U9.2), PAGE02 Board Connector (CON4.41)
9134_INT: PAGE07 HDMI OUT (U9.24), PAGE02 Board Connector (CON4.15)
9134_MCLK: PAGE07 HDMI OUT (U9.5), PAGE02 Board Connector (CON4.33)
9134_nRESET: PAGE07 HDMI OUT (U9.25), PAGE02 Board Connector (CON4.13)
9134_SCK: PAGE07 HDMI OUT (U9.11), PAGE02 Board Connector (CON4.17)
9134_SCL: PAGE07 HDMI OUT (R48.1 U9.48), PAGE02 Board Connector (CON4.16)
9134_SD0: PAGE07 HDMI OUT (U9.9), PAGE02 Board Connector (CON4.23)
9134_SD1: PAGE07 HDMI OUT (U9.8), PAGE02 Board Connector (CON4.25)
9134_SD2: PAGE07 HDMI OUT (U9.7), PAGE02 Board Connector (CON4.27)
9134_SD3: PAGE07 HDMI OUT (U9.6), PAGE02 Board Connector (CON4.31)
9134_SDA: PAGE07 HDMI OUT (R49.1 U9.49), PAGE02 Board Connector (CON4.14)
9134_SPDIF: PAGE07 HDMI OUT (U9.4), PAGE02 Board Connector (CON4.35)
9134_VS: PAGE07 HDMI OUT (U9.3), PAGE02 Board Connector (CON4.37)
9134_WS: PAGE07 HDMI OUT (U9.10), PAGE02 Board Connector (CON4.21)
FPGA_TCK: PAGE03 JTAG (R3.1), PAGE02 Board Connector (CON1.78)
FPGA_TDI: PAGE03 JTAG (R4.1), PAGE02 Board Connector (CON1.80)
FPGA_TDO: PAGE03 JTAG (R5.1), PAGE02 Board Connector (CON1.79)
FPGA_TMS: PAGE03 JTAG (R6.1), PAGE02 Board Connector (CON1.77)
IO1_1N: PAGE13 EX Connector (RN1.3), PAGE02 Board Connector (CON2.51)
IO1_1P: PAGE13 EX Connector (RN1.4), PAGE02 Board Connector (CON2.53)
IO1_2N: PAGE13 EX Connector (RN1.1), PAGE02 Board Connector (CON2.45)
IO1_2P: PAGE13 EX Connector (RN1.2), PAGE02 Board Connector (CON2.47)
IO1_3N: PAGE13 EX Connector (RN3.3), PAGE02 Board Connector (CON2.41)
IO1_3P: PAGE13 EX Connector (RN3.4), PAGE02 Board Connector (CON2.43)
IO1_4N: PAGE13 EX Connector (RN3.1), PAGE02 Board Connector (CON4.44)
IO1_4P: PAGE13 EX Connector (RN3.2), PAGE02 Board Connector (CON4.42)
IO1_5N: PAGE13 EX Connector (RN5.3), PAGE02 Board Connector (CON4.58)
IO1_5P: PAGE13 EX Connector (RN5.4), PAGE02 Board Connector (CON4.56)
IO1_6N: PAGE13 EX Connector (RN5.1), PAGE02 Board Connector (CON4.67)
IO1_6P: PAGE13 EX Connector (RN5.2), PAGE02 Board Connector (CON4.65)
IO1_7N: PAGE13 EX Connector (RN7.3), PAGE02 Board Connector (CON4.68)
IO1_7P: PAGE13 EX Connector (RN7.4), PAGE02 Board Connector (CON4.66)
IO1_8N: PAGE13 EX Connector (RN7.1), PAGE02 Board Connector (CON4.73)
IO1_8P: PAGE13 EX Connector (RN7.2), PAGE02 Board Connector (CON4.71)
IO1_9N: PAGE13 EX Connector (RN9.3), PAGE02 Board Connector (CON4.74)
IO1_9P: PAGE13 EX Connector (RN9.4), PAGE02 Board Connector (CON4.72)
IO1_10N: PAGE13 EX Connector (RN9.1), PAGE02 Board Connector (CON4.78)
IO1_10P: PAGE13 EX Connector (RN9.2), PAGE02 Board Connector (CON4.76)
IO1_11N: PAGE13 EX Connector (RN11.3), PAGE02 Board Connector (CON4.80)
IO1_11P: PAGE13 EX Connector (RN11.4), PAGE02 Board Connector (CON4.79)
IO1_12N: PAGE13 EX Connector (RN11.1), PAGE02 Board Connector (CON2.15)
IO1_12P: PAGE13 EX Connector (RN11.2), PAGE02 Board Connector (CON2.17)
IO1_13N: PAGE13 EX Connector (RN13.3), PAGE02 Board Connector (CON2.5)
IO1_13P: PAGE13 EX Connector (RN13.4), PAGE02 Board Connector (CON2.7)
IO1_14N: PAGE13 EX Connector (RN13.1), PAGE02 Board Connector (CON2.6)
IO1_14P: PAGE13 EX Connector (RN13.2), PAGE02 Board Connector (CON2.8)
IO1_15N: PAGE13 EX Connector (RN15.3), PAGE02 Board Connector (CON2.2)
IO1_15P: PAGE13 EX Connector (RN15.4), PAGE02 Board Connector (CON2.4)
IO1_16N: PAGE13 EX Connector (RN15.1), PAGE02 Board Connector (CON3.41)
IO1_16P: PAGE13 EX Connector (RN15.2), PAGE02 Board Connector (CON3.43)
IO1_17N: PAGE13 EX Connector (RN17.1), PAGE02 Board Connector (CON3.37)
IO1_17P: PAGE13 EX Connector (RN17.2), PAGE02 Board Connector (CON3.35)
IO2_1N: PAGE13 EX Connector (RN2.3), PAGE02 Board Connector (CON2.13)
IO2_1P: PAGE13 EX Connector (RN2.4), PAGE02 Board Connector (CON2.11)
IO2_2N: PAGE13 EX Connector (RN2.1), PAGE02 Board Connector (CON2.18)
IO2_2P: PAGE13 EX Connector (RN2.2), PAGE02 Board Connector (CON2.16)
IO2_3N: PAGE13 EX Connector (RN4.3), PAGE02 Board Connector (CON2.28)
IO2_3P: PAGE13 EX Connector (RN4.4), PAGE02 Board Connector (CON2.26)
IO2_4N: PAGE13 EX Connector (RN4.1), PAGE02 Board Connector (CON2.34)
IO2_4P: PAGE13 EX Connector (RN4.2), PAGE02 Board Connector (CON2.32)
IO2_5N: PAGE13 EX Connector (RN6.3), PAGE02 Board Connector (CON2.38)
IO2_5P: PAGE13 EX Connector (RN6.4), PAGE02 Board Connector (CON2.36)
IO2_6N: PAGE13 EX Connector (RN6.1), PAGE02 Board Connector (CON2.44)
IO2_6P: PAGE13 EX Connector (RN6.2), PAGE02 Board Connector (CON2.42)
IO2_7N: PAGE13 EX Connector (RN8.3), PAGE02 Board Connector (CON2.48)
IO2_7P: PAGE13 EX Connector (RN8.4), PAGE02 Board Connector (CON2.46)
IO2_8N: PAGE13 EX Connector (RN8.1), PAGE02 Board Connector (CON2.54)
IO2_8P: PAGE13 EX Connector (RN8.2), PAGE02 Board Connector (CON2.52)
IO2_9N: PAGE13 EX Connector (RN10.3), PAGE02 Board Connector (CON2.58)
IO2_9P: PAGE13 EX Connector (RN10.4), PAGE02 Board Connector (CON2.56)
IO2_10N: PAGE13 EX Connector (RN10.1), PAGE02 Board Connector (CON2.64)
IO2_10P: PAGE13 EX Connector (RN10.2), PAGE02 Board Connector (CON2.62)
IO2_11N: PAGE13 EX Connector (RN12.3), PAGE02 Board Connector (CON2.63)
IO2_11P: PAGE13 EX Connector (RN12.4), PAGE02 Board Connector (CON2.61)
IO2_12N: PAGE13 EX Connector (RN12.1), PAGE02 Board Connector (CON2.68)
IO2_12P: PAGE13 EX Connector (RN12.2), PAGE02 Board Connector (CON2.66)
IO2_13N: PAGE13 EX Connector (RN14.3), PAGE02 Board Connector (CON2.78)
IO2_13P: PAGE13 EX Connector (RN14.4), PAGE02 Board Connector (CON2.76)
IO2_14N: PAGE13 EX Connector (RN14.1), PAGE02 Board Connector (CON2.74)
IO2_14P: PAGE13 EX Connector (RN14.2), PAGE02 Board Connector (CON2.72)
IO2_15N: PAGE13 EX Connector (RN16.3), PAGE02 Board Connector (CON2.67)
IO2_15P: PAGE13 EX Connector (RN16.4), PAGE02 Board Connector (CON2.65)
IO2_16N: PAGE13 EX Connector (RN16.1), PAGE02 Board Connector (CON2.73)
IO2_16P: PAGE13 EX Connector (RN16.2), PAGE02 Board Connector (CON2.71)
IO2_17N: PAGE13 EX Connector (RN18.1), PAGE02 Board Connector (CON2.77)
IO2_17P: PAGE13 EX Connector (RN18.2), PAGE02 Board Connector (CON2.75)
OTG_CLK: PAGE06 HOST USB X 4 (R37.1), PAGE02 Board Connector (CON1.52)
OTG_DATA0: PAGE06 HOST USB X 4 (U7.3), PAGE02 Board Connector (CON1.56)
OTG_DATA1: PAGE06 HOST USB X 4 (U7.4), PAGE02 Board Connector (CON1.58)
OTG_DATA2: PAGE06 HOST USB X 4 (U7.5), PAGE02 Board Connector (CON1.62)
OTG_DATA3: PAGE06 HOST USB X 4 (U7.6), PAGE02 Board Connector (CON1.64)
OTG_DATA4: PAGE06 HOST USB X 4 (U7.7), PAGE02 Board Connector (CON1.66)
OTG_DATA5: PAGE06 HOST USB X 4 (U7.9), PAGE02 Board Connector (CON1.68)
OTG_DATA6: PAGE06 HOST USB X 4 (U7.10), PAGE02 Board Connector (CON1.72)
OTG_DATA7: PAGE06 HOST USB X 4 (U7.13), PAGE02 Board Connector (CON1.74)
OTG_DIR: PAGE06 HOST USB X 4 (U7.31), PAGE02 Board Connector (CON1.48)
OTG_NXT: PAGE06 HOST USB X 4 (U7.2), PAGE02 Board Connector (CON1.54)
OTG_RESET: PAGE06 HOST USB X 4 (D2.1 D3.1), PAGE02 Board Connector (CON1.33)
OTG_STP: PAGE06 HOST USB X 4 (U7.29), PAGE02 Board Connector (CON1.46)
PHY1_MDC: PAGE05 PS Ethernet1 (U6.13), PAGE02 Board Connector (CON1.42)
PHY1_MDIO: PAGE05 PS Ethernet1 (R1027.1 U6.14), PAGE02 Board Connector (CON1.44)
PHY1_RESET: PAGE05 PS Ethernet1 (D35.1), PAGE02 Board Connector (CON1.31)
PHY1_RXCK: PAGE05 PS Ethernet1 (R1031.2), PAGE02 Board Connector (CON1.38)
PHY1_RXCTL: PAGE05 PS Ethernet1 (R1032.2), PAGE02 Board Connector (CON1.36)
PHY1_RXD0: PAGE05 PS Ethernet1 (RN19.4), PAGE02 Board Connector (CON1.34)
PHY1_RXD1: PAGE05 PS Ethernet1 (RN19.3), PAGE02 Board Connector (CON1.32)
PHY1_RXD2: PAGE05 PS Ethernet1 (RN19.2), PAGE02 Board Connector (CON1.28)
PHY1_RXD3: PAGE05 PS Ethernet1 (RN19.1), PAGE02 Board Connector (CON1.26)
PHY1_TXCK: PAGE05 PS Ethernet1 (U6.20), PAGE02 Board Connector (CON1.22)
PHY1_TXCTL: PAGE05 PS Ethernet1 (U6.19), PAGE02 Board Connector (CON1.24)
PHY1_TXD0: PAGE05 PS Ethernet1 (U6.18), PAGE02 Board Connector (CON1.12)
PHY1_TXD1: PAGE05 PS Ethernet1 (U6.17), PAGE02 Board Connector (CON1.14)
PHY1_TXD2: PAGE05 PS Ethernet1 (U6.16), PAGE02 Board Connector (CON1.16)
PHY1_TXD3: PAGE05 PS Ethernet1 (U6.15), PAGE02 Board Connector (CON1.18)
PHY2_MDC: PAGE08 PL Ethernet2 (U10.13), PAGE02 Board Connector (CON3.3)
PHY2_MDIO: PAGE08 PL Ethernet2 (R1043.1 U10.14), PAGE02 Board Connector (CON3.1)
PHY2_RESET: PAGE08 PL Ethernet2 (C1510.1 R1060.1 U10.12), PAGE02 Board Connector (CON3.2)
PHY2_RXCK: PAGE08 PL Ethernet2 (R1048.2), PAGE02 Board Connector (CON3.5)
PHY2_RXCTL: PAGE08 PL Ethernet2 (R1049.2), PAGE02 Board Connector (CON3.7)
PHY2_RXD0: PAGE08 PL Ethernet2 (RN20.4), PAGE02 Board Connector (CON3.11)
PHY2_RXD1: PAGE08 PL Ethernet2 (RN20.3), PAGE02 Board Connector (CON3.13)
PHY2_RXD2: PAGE08 PL Ethernet2 (RN20.2), PAGE02 Board Connector (CON3.15)
PHY2_RXD3: PAGE08 PL Ethernet2 (RN20.1), PAGE02 Board Connector (CON3.17)
PHY2_TXCK: PAGE08 PL Ethernet2 (U10.20), PAGE02 Board Connector (CON3.23)
PHY2_TXCTL: PAGE08 PL Ethernet2 (U10.19), PAGE02 Board Connector (CON3.21)
PHY2_TXD0: PAGE08 PL Ethernet2 (U10.18), PAGE02 Board Connector (CON3.33)
PHY2_TXD1: PAGE08 PL Ethernet2 (U10.17), PAGE02 Board Connector (CON3.31)
PHY2_TXD2: PAGE08 PL Ethernet2 (U10.16), PAGE02 Board Connector (CON3.27)
PHY2_TXD3: PAGE08 PL Ethernet2 (U10.15), PAGE02 Board Connector (CON3.25)
PHY3_MDC: PAGE09 PL Ethernet3 (U11.13), PAGE02 Board Connector (CON3.34)
PHY3_MDIO: PAGE09 PL Ethernet3 (R1079.1 U11.14), PAGE02 Board Connector (CON3.36)
PHY3_RESET: PAGE09 PL Ethernet3 (C1527.1 R1077.1 U11.12), PAGE02 Board Connector (CON3.38)
PHY3_RXCK: PAGE09 PL Ethernet3 (R1066.2), PAGE02 Board Connector (CON3.32)
PHY3_RXCTL: PAGE09 PL Ethernet3 (R1065.2), PAGE02 Board Connector (CON3.28)
PHY3_RXD0: PAGE09 PL Ethernet3 (RN21.4), PAGE02 Board Connector (CON3.26)
PHY3_RXD1: PAGE09 PL Ethernet3 (RN21.3), PAGE02 Board Connector (CON3.24)
PHY3_RXD2: PAGE09 PL Ethernet3 (RN21.2), PAGE02 Board Connector (CON3.22)
PHY3_RXD3: PAGE09 PL Ethernet3 (RN21.1), PAGE02 Board Connector (CON3.18)
PHY3_TXCK: PAGE09 PL Ethernet3 (U11.20), PAGE02 Board Connector (CON3.14)
PHY3_TXCTL: PAGE09 PL Ethernet3 (U11.19), PAGE02 Board Connector (CON3.16)
PHY3_TXD0: PAGE09 PL Ethernet3 (U11.18), PAGE02 Board Connector (CON3.4)
PHY3_TXD1: PAGE09 PL Ethernet3 (U11.17), PAGE02 Board Connector (CON3.6)
PHY3_TXD2: PAGE09 PL Ethernet3 (U11.16), PAGE02 Board Connector (CON3.8)
PHY3_TXD3: PAGE09 PL Ethernet3 (U11.15), PAGE02 Board Connector (CON3.12)
PHY4_MDC: PAGE10 PL Ethernet4 (U12.13), PAGE02 Board Connector (CON3.74)
PHY4_MDIO: PAGE10 PL Ethernet4 (R1097.1 U12.14), PAGE02 Board Connector (CON3.76)
PHY4_RESET: PAGE10 PL Ethernet4 (C1544.1 R1095.1 U12.12), PAGE02 Board Connector (CON3.78)
PHY4_RXCK: PAGE10 PL Ethernet4 (R1084.2), PAGE02 Board Connector (CON3.72)
PHY4_RXCTL: PAGE10 PL Ethernet4 (R1083.2), PAGE02 Board Connector (CON3.68)
PHY4_RXD0: PAGE10 PL Ethernet4 (RN22.4), PAGE02 Board Connector (CON3.66)
PHY4_RXD1: PAGE10 PL Ethernet4 (RN22.3), PAGE02 Board Connector (CON3.64)
PHY4_RXD2: PAGE10 PL Ethernet4 (RN22.2), PAGE02 Board Connector (CON3.62)
PHY4_RXD3: PAGE10 PL Ethernet4 (RN22.1), PAGE02 Board Connector (CON3.58)
PHY4_TXCK: PAGE10 PL Ethernet4 (U12.20), PAGE02 Board Connector (CON3.54)
PHY4_TXCTL: PAGE10 PL Ethernet4 (U12.19), PAGE02 Board Connector (CON3.56)
PHY4_TXD0: PAGE10 PL Ethernet4 (U12.18), PAGE02 Board Connector (CON3.44)
PHY4_TXD1: PAGE10 PL Ethernet4 (U12.17), PAGE02 Board Connector (CON3.46)
PHY4_TXD2: PAGE10 PL Ethernet4 (U12.16), PAGE02 Board Connector (CON3.48)
PHY4_TXD3: PAGE10 PL Ethernet4 (U12.15), PAGE02 Board Connector (CON3.52)
PHY5_MDC: PAGE11 PL Ethernet5 (U13.13), PAGE02 Board Connector (CON3.47)
PHY5_MDIO: PAGE11 PL Ethernet5 (R1114.1 U13.14), PAGE02 Board Connector (CON3.45)
PHY5_RESET: PAGE11 PL Ethernet5 (C1561.1 R1113.1 U13.12), PAGE02 Board Connector (CON3.42)
PHY5_RXCK: PAGE11 PL Ethernet5 (R1101.2), PAGE02 Board Connector (CON3.51)
PHY5_RXCTL: PAGE11 PL Ethernet5 (R1102.2), PAGE02 Board Connector (CON3.53)
PHY5_RXD0: PAGE11 PL Ethernet5 (RN23.4), PAGE02 Board Connector (CON3.55)
PHY5_RXD1: PAGE11 PL Ethernet5 (RN23.3), PAGE02 Board Connector (CON3.57)
PHY5_RXD2: PAGE11 PL Ethernet5 (RN23.2), PAGE02 Board Connector (CON3.61)
PHY5_RXD3: PAGE11 PL Ethernet5 (RN23.1), PAGE02 Board Connector (CON3.63)
PHY5_TXCK: PAGE11 PL Ethernet5 (U13.20), PAGE02 Board Connector (CON3.67)
PHY5_TXCTL: PAGE11 PL Ethernet5 (U13.19), PAGE02 Board Connector (CON3.65)
PHY5_TXD0: PAGE11 PL Ethernet5 (U13.18), PAGE02 Board Connector (CON3.77)
PHY5_TXD1: PAGE11 PL Ethernet5 (U13.17), PAGE02 Board Connector (CON3.75)
PHY5_TXD2: PAGE11 PL Ethernet5 (U13.16), PAGE02 Board Connector (CON3.73)
PHY5_TXD3: PAGE11 PL Ethernet5 (U13.15), PAGE02 Board Connector (CON3.71)
PL_KEY: PAGE12 KEY and LED (R129.2), PAGE02 Board Connector (CON4.4)
PL_LED: PAGE12 KEY and LED (R133.1), PAGE02 Board Connector (CON4.2)
PS_KEY: PAGE12 KEY and LED (R121.2), PAGE02 Board Connector (CON1.37)
PS_LED: PAGE12 KEY and LED (R131.1), PAGE02 Board Connector (CON1.35)
SD_CD: PAGE04 SD Card and UART (R19.1 R20.2), PAGE02 Board Connector (CON1.57)
SD_CLK: PAGE04 SD Card and UART (U5.9), PAGE02 Board Connector (CON1.61)
SD_CMD: PAGE04 SD Card and UART (U5.4), PAGE02 Board Connector (CON1.67)
SD_D0: PAGE04 SD Card and UART (U5.6), PAGE02 Board Connector (CON1.65)
SD_D1: PAGE04 SD Card and UART (U5.7), PAGE02 Board Connector (CON1.63)
SD_D2: PAGE04 SD Card and UART (U5.1), PAGE02 Board Connector (CON1.73)
SD_D3: PAGE04 SD Card and UART (U5.3), PAGE02 Board Connector (CON1.71)
UART_RX: PAGE04 SD Card and UART (U4.5), PAGE02 Board Connector (CON1.11)
UART_TX: PAGE04 SD Card and UART (U4.4), PAGE02 Board Connector (CON1.13)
